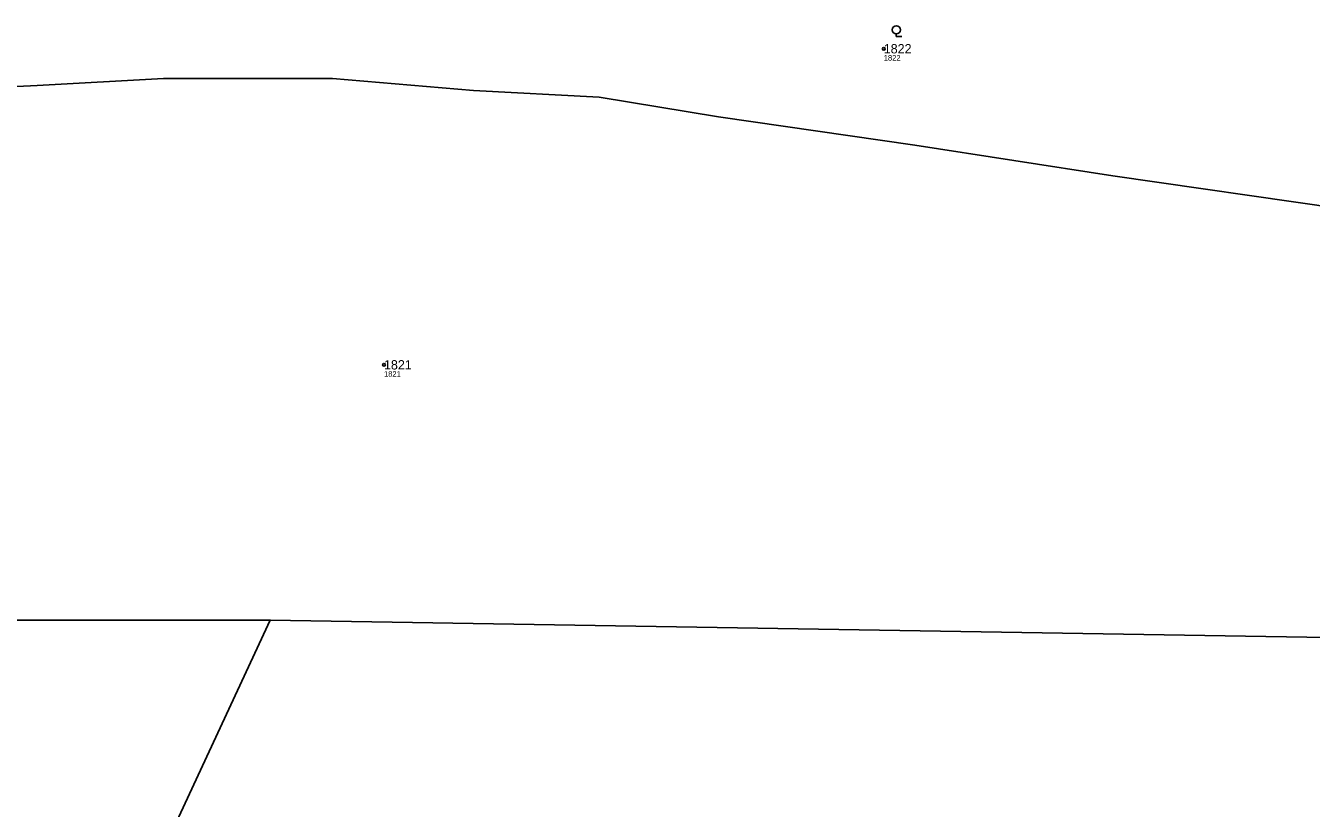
# Model space of a CAD drawing. Extents: x -770088 to -765625, y -1057899 to -1053934.
# Drawn here: x -766720.7 to -766486.3, y -1055281.6 to -1055138.9 of the extents above; entities that cross this region are included whole.
import ezdxf

# ---------------------------------------------------------------- set-up
doc = ezdxf.new("R2010")
doc.units = 0
for name, color, linetype in [('Definiční body', 7, 'Continuous'), ('Hranice parcel', 7, 'Continuous'), ('Parcelní čísla', 7, 'Continuous'), ('Polygon parcely', 7, 'Continuous'), ('Značky kultur', 7, 'Continuous')]:
    doc.layers.add(name, color=color, linetype=linetype)

msp = doc.modelspace()

# ---------------------------------------------------------------- linework, layer by layer
at = {"layer": 'Definiční body'}
for centre in [(-766564.29, -1055143.1), (-766655.41, -1055200.75)]:
    msp.add_circle(centre, 0.25, dxfattribs=at)
at = {"layer": 'Hranice parcel'}
msp.add_line((-766676.14, -1055247.31), (-766843.53, -1055247.34), dxfattribs=at)
for points in [[(-766391.12, -1055195.24), (-766447.93, -1055182.33), (-766481.16, -1055172.21), (-766522.51, -1055166.31), (-766558.65, -1055160.71), (-766594.45, -1055155.51), (-766616.16, -1055151.96), (-766639.11, -1055150.73), (-766664.78, -1055148.51), (-766695.64, -1055148.53), (-766718.67, -1055149.78), (-766750.96, -1055151.41), (-766776.77, -1055153.97), (-766799.75, -1055153.9), (-766818.37, -1055151.68)], [(-766980.09, -1055357.81), (-766858.93, -1055368.87), (-766737.77, -1055379.93), (-766676.14, -1055247.31)], [(-766676.14, -1055247.31), (-766553.92, -1055249.32), (-766431.56, -1055251.34)]]:
    msp.add_lwpolyline(points, dxfattribs=at)
at = {"layer": 'Polygon parcely'}
for points in [[(-766639.11, -1055150.73), (-766664.78, -1055148.51), (-766695.64, -1055148.53), (-766718.67, -1055149.78), (-766750.96, -1055151.41), (-766776.77, -1055153.97), (-766799.75, -1055153.9), (-766818.37, -1055151.68), (-766828.63, -1055151.7), (-766840.15, -1055152.29), (-766843.79, -1055152.66), (-766843.53, -1055247.34), (-766676.14, -1055247.31), (-766553.92, -1055249.32), (-766431.56, -1055251.34), (-766391.12, -1055195.24), (-766447.93, -1055182.33), (-766481.16, -1055172.21), (-766522.51, -1055166.31), (-766558.65, -1055160.71), (-766594.45, -1055155.51), (-766616.16, -1055151.96)], [(-767051.19, -1055490.89), (-767008.94, -1055506.39), (-766902.15, -1055547.61), (-766863.56, -1055564.81), (-766833.9, -1055579.4), (-766784.3, -1055607.49), (-766755.11, -1055627.17), (-766715.17, -1055661.57), (-766620.63, -1055524.83), (-766526.1, -1055388.09), (-766431.56, -1055251.34), (-766553.92, -1055249.32), (-766676.14, -1055247.31), (-766737.77, -1055379.93), (-766858.93, -1055368.87), (-766980.09, -1055357.81)], [(-766980.09, -1055357.81), (-766858.93, -1055368.87), (-766737.77, -1055379.93), (-766676.14, -1055247.31), (-766843.53, -1055247.34), (-766864.14, -1055247.34), (-766931.23, -1055247.35), (-766969.28, -1055247.45), (-766971.09, -1055265.9), (-766979.46, -1055351.42)]]:
    msp.add_lwpolyline(points, close=True, dxfattribs=at)
msp.add_lwpolyline([(-766750.96, -1055151.41), (-766718.67, -1055149.78), (-766695.64, -1055148.53), (-766664.78, -1055148.51), (-766639.11, -1055150.73), (-766616.16, -1055151.96), (-766594.45, -1055155.51), (-766558.65, -1055160.71), (-766522.51, -1055166.31), (-766481.16, -1055172.21)], dxfattribs=at)
at = {"layer": 'Značky kultur'}
for p, q in [((-766562.01, -1055140.4), (-766562.01, -1055140.9)), ((-766562.01, -1055140.9), (-766561.01, -1055140.9))]:
    msp.add_line(p, q, dxfattribs=at)
msp.add_circle((-766562.01, -1055139.65), 0.75, dxfattribs=at)

# ---------------------------------------------------------------- texts
at = {"layer": 'Definiční body'}
for s, p in [('1822', (-766564.29, -1055145.26)), ('1821', (-766655.41, -1055202.91))]:
    msp.add_text(s, height=1, dxfattribs=at).set_placement(p)
at = {"layer": 'Parcelní čísla'}
for s, p in [('1822', (-766564.29, -1055143.95)), ('1821', (-766655.41, -1055201.6))]:
    msp.add_text(s, height=1.7, dxfattribs=at).set_placement(p)

doc.saveas('drawing.dxf')
